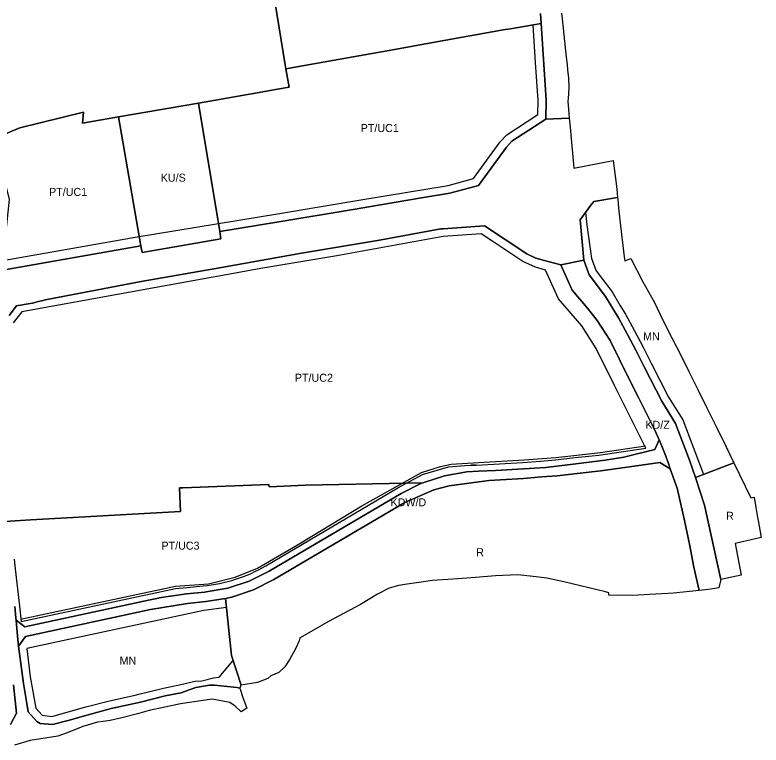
# Model space of a CAD drawing. Extents: x 7436680 to 7439366, y 5548361 to 5550775.
# Drawn here: x 7438434 to 7439366, y 5548558 to 5549471 of the extents above; entities that cross this region are included whole.
import ezdxf

# ---------------------------------------------------------------- set-up
doc = ezdxf.new("R2010")
doc.units = 0
for name, color, linetype in [('linie_rozgraniczajace', 7, 'Continuous'), ('linie_zabudowy_azurowe', 7, 'Continuous'), ('linie_zabudowy_nieprzekraczalne', 7, 'Continuous'), ('oznaczenia_przeznaczen', 7, 'Continuous')]:
    doc.layers.add(name, color=color, linetype=linetype)

msp = doc.modelspace()

# ---------------------------------------------------------------- linework, layer by layer
at = {"layer": 'linie_rozgraniczajace'}
for points in [[(7438758.39, 5549488.21), (7438771.55, 5549408.46), (7438772.42, 5549403.54), (7438772.37, 5549403.53), (7438776.39, 5549380.53), (7438762.06, 5549377.99), (7438736.43, 5549373.59), (7438712.84, 5549369.45), (7438662.92, 5549360.56), (7438563.16, 5549343.44), (7438518.12, 5549335.61), (7438519.44, 5549349.55), (7438440, 5549329.59), (7438398.71, 5549312.9)], [(7439090.49, 5549472.78), (7439091.28, 5549460.46), (7439081.9, 5549458.81), (7439053.2, 5549453.78), (7439046.51, 5549452.59), (7438955.8, 5549436.39), (7438906.16, 5549427.5), (7438856.52, 5549418.6), (7438807.29, 5549409.78), (7438772.42, 5549403.54), (7438771.55, 5549408.46), (7438758.39, 5549488.21)], [(7439116.62, 5549473.09), (7439117.57, 5549466.21), (7439122.55, 5549418.11), (7439123.79, 5549408.88), (7439124.43, 5549401.86), (7439125.43, 5549392.18), (7439125.83, 5549379.29), (7439125.15, 5549366.28), (7439124.52, 5549363.27), (7439125.91, 5549347.92), (7439126.45, 5549341.98), (7439097.19, 5549340.81), (7439097.48, 5549364.34), (7439091.28, 5549460.46), (7439090.49, 5549472.78)], [(7438420.86, 5549152.06), (7438591.21, 5549182.25), (7438592.66, 5549173.93), (7438621.57, 5549178.81), (7438633.67, 5549180.91), (7438691.19, 5549191.04), (7438689.86, 5549200.22), (7438763.32, 5549212.38), (7438853.79, 5549227.43), (7438944.27, 5549242.48), (7438977.15, 5549247.95), (7439012.92, 5549257.77), (7439047.87, 5549305.78), (7439054.9, 5549313.26), (7439097.19, 5549340.81), (7439126.45, 5549341.98), (7439127.48, 5549330.64), (7439129.18, 5549311.96), (7439131.67, 5549284.51), (7439132.15, 5549279.27), (7439181.32, 5549288.86), (7439186.07, 5549253.42), (7439186.93, 5549242.78), (7439157.21, 5549237.85), (7439153.39, 5549233.08), (7439140.09, 5549214.87), (7439144.6, 5549164.19), (7439115.92, 5549158.3), (7439100.32, 5549162.61), (7439084.73, 5549166.92), (7439073.32, 5549172.36), (7439020.58, 5549207.34), (7438968.76, 5549203.62), (7438965.87, 5549203.41), (7438889.32, 5549189.43), (7438887, 5549189.04), (7438791.89, 5549173.1), (7438691.9, 5549155.13), (7438591.6, 5549137.47), (7438475.87, 5549115.65), (7438473.59, 5549115.06), (7438470.21, 5549114.2), (7438468.65, 5549113.81), (7438467.27, 5549113.46), (7438462.9, 5549112.4), (7438457.32, 5549111.09), (7438455.53, 5549110.68), (7438450.12, 5549109.76), (7438445.37, 5549108.86), (7438440.88, 5549107.99), (7438437.8, 5549107.46), (7438435.66, 5549107.09), (7438426.37, 5549095.2)], [(7438426.37, 5549095.2), (7438435.66, 5549107.09), (7438437.8, 5549107.46), (7438440.88, 5549107.99), (7438445.37, 5549108.86), (7438450.12, 5549109.76), (7438455.53, 5549110.68), (7438457.32, 5549111.09), (7438462.9, 5549112.4), (7438467.27, 5549113.46), (7438468.65, 5549113.81), (7438470.21, 5549114.2), (7438473.59, 5549115.06), (7438475.87, 5549115.65), (7438591.6, 5549137.47), (7438691.9, 5549155.13), (7438791.89, 5549173.1), (7438887, 5549189.04), (7438889.32, 5549189.43), (7438965.87, 5549203.41), (7438968.76, 5549203.62), (7439020.58, 5549207.34), (7439073.32, 5549172.36), (7439084.73, 5549166.92), (7439100.32, 5549162.61), (7439115.92, 5549158.3), (7439130.05, 5549126.55), (7439149.34, 5549104.27), (7439161.5, 5549088.8), (7439177.48, 5549063.6), (7439201.05, 5549016.44), (7439213.39, 5548991.75), (7439230.43, 5548957.66), (7439230.68, 5548957.16), (7439230.93, 5548956.66), (7439231.18, 5548956.16), (7439231.42, 5548955.66), (7439231.67, 5548955.16), (7439231.91, 5548954.66), (7439232.16, 5548954.16), (7439232.4, 5548953.66), (7439232.64, 5548953.16), (7439232.89, 5548952.66), (7439233.13, 5548952.16), (7439233.37, 5548951.65), (7439233.61, 5548951.15), (7439233.85, 5548950.65), (7439234.09, 5548950.15), (7439234.32, 5548949.64), (7439234.56, 5548949.14), (7439234.8, 5548948.64), (7439235.03, 5548948.13), (7439235.27, 5548947.63), (7439235.5, 5548947.12), (7439235.73, 5548946.62), (7439235.97, 5548946.11), (7439236.2, 5548945.6), (7439236.43, 5548945.1), (7439236.66, 5548944.59), (7439236.89, 5548944.08), (7439237.12, 5548943.58), (7439237.35, 5548943.07), (7439237.58, 5548942.56), (7439237.8, 5548942.05), (7439238.03, 5548941.54), (7439238.25, 5548941.03), (7439238.48, 5548940.52), (7439238.7, 5548940.01), (7439238.91, 5548939.54), (7439233.43, 5548927.55), (7439194.72, 5548918.03), (7439171.58, 5548914.26), (7439134.72, 5548909.36), (7439097.34, 5548905.11), (7439034.42, 5548901.17), (7439013.09, 5548900.52), (7438998.51, 5548899.54), (7438970.49, 5548894.64), (7438943.44, 5548885.86), (7438943.44, 5548885.86), (7438796.98, 5548882.79), (7438751.28, 5548880.69), (7438750.95, 5548883.88), (7438643.55, 5548879.48), (7438639.45, 5548879.31), (7438640.66, 5548849.84), (7438453.56, 5548839.39), (7438421.02, 5548837.58)], [(7439115.92, 5549158.3), (7439144.6, 5549164.19), (7439151.33, 5549145.97), (7439171.82, 5549119), (7439188.06, 5549091.99), (7439199.19, 5549071.18), (7439209.97, 5549050.74), (7439220.07, 5549030.99), (7439242.02, 5548987.84), (7439259.36, 5548960.09), (7439276.81, 5548914.25), (7439284.15, 5548892.38), (7439295.7, 5548857.98), (7439315.91, 5548764.71), (7439313.53, 5548754.52), (7439300.65, 5548752.42), (7439288.83, 5548751.19), (7439282.04, 5548780.33), (7439276.95, 5548809.24), (7439270.65, 5548838.72), (7439261.28, 5548878.96), (7439252.74, 5548903.34), (7439249.54, 5548912.49), (7439249.51, 5548912.57), (7439249.33, 5548913.09), (7439249.14, 5548913.62), (7439248.96, 5548914.14), (7439248.77, 5548914.67), (7439248.58, 5548915.19), (7439248.39, 5548915.71), (7439248.2, 5548916.24), (7439248.01, 5548916.76), (7439247.82, 5548917.28), (7439247.63, 5548917.81), (7439247.44, 5548918.33), (7439247.25, 5548918.85), (7439247.05, 5548919.37), (7439246.86, 5548919.9), (7439246.66, 5548920.42), (7439246.47, 5548920.94), (7439246.27, 5548921.46), (7439246.08, 5548921.98), (7439245.88, 5548922.5), (7439245.68, 5548923.02), (7439245.48, 5548923.54), (7439245.28, 5548924.06), (7439245.08, 5548924.58), (7439244.88, 5548925.1), (7439244.67, 5548925.62), (7439244.47, 5548926.13), (7439244.27, 5548926.65), (7439244.06, 5548927.17), (7439243.86, 5548927.69), (7439243.65, 5548928.2), (7439243.44, 5548928.72), (7439243.24, 5548929.24), (7439243.22, 5548929.28), (7439243.03, 5548929.75), (7439242.82, 5548930.27), (7439242.61, 5548930.79), (7439242.4, 5548931.3), (7439242.19, 5548931.82), (7439241.97, 5548932.33), (7439241.76, 5548932.85), (7439241.55, 5548933.36), (7439241.33, 5548933.87), (7439241.12, 5548934.39), (7439240.9, 5548934.9), (7439240.68, 5548935.41), (7439240.47, 5548935.93), (7439240.25, 5548936.44), (7439240.03, 5548936.95), (7439239.81, 5548937.46), (7439239.59, 5548937.97), (7439239.37, 5548938.48), (7439239.15, 5548938.99), (7439238.93, 5548939.5), (7439238.91, 5548939.54), (7439238.7, 5548940.01), (7439238.48, 5548940.52), (7439238.25, 5548941.03), (7439238.03, 5548941.54), (7439237.8, 5548942.05), (7439237.58, 5548942.56), (7439237.35, 5548943.07), (7439237.12, 5548943.58), (7439236.89, 5548944.08), (7439236.66, 5548944.59), (7439236.43, 5548945.1), (7439236.2, 5548945.6), (7439235.97, 5548946.11), (7439235.73, 5548946.62), (7439235.5, 5548947.12), (7439235.27, 5548947.63), (7439235.03, 5548948.13), (7439234.8, 5548948.64), (7439234.56, 5548949.14), (7439234.32, 5548949.64), (7439234.09, 5548950.15), (7439233.85, 5548950.65)], [(7439233.85, 5548950.65), (7439233.61, 5548951.15), (7439233.37, 5548951.65), (7439233.13, 5548952.16), (7439232.89, 5548952.66), (7439232.64, 5548953.16), (7439232.4, 5548953.66), (7439232.16, 5548954.16), (7439231.91, 5548954.66), (7439231.67, 5548955.16), (7439231.42, 5548955.66), (7439231.18, 5548956.16), (7439230.93, 5548956.66), (7439230.68, 5548957.16), (7439230.43, 5548957.66), (7439213.39, 5548991.75), (7439201.05, 5549016.44), (7439177.48, 5549063.6), (7439161.5, 5549088.8), (7439149.34, 5549104.27), (7439130.05, 5549126.55), (7439115.92, 5549158.3)], [(7438435.1, 5548713.87), (7438446.18, 5548705.73), (7438600.78, 5548738.94), (7438612.95, 5548741.55), (7438613.84, 5548741.74), (7438648.31, 5548746.98), (7438670.99, 5548749.12), (7438672.55, 5548749.27), (7438699.97, 5548754.08), (7438726.42, 5548762.77), (7438751.35, 5548775.16), (7438916.46, 5548872.54), (7438941.91, 5548885.23), (7438943.44, 5548885.86), (7438943.44, 5548885.86), (7438970.49, 5548894.64), (7438998.51, 5548899.54), (7439013.09, 5548900.52), (7439034.42, 5548901.17), (7439097.34, 5548905.11), (7439134.72, 5548909.36), (7439171.58, 5548914.26), (7439194.72, 5548918.03), (7439233.43, 5548927.55), (7439238.91, 5548939.54), (7439238.93, 5548939.5), (7439239.15, 5548938.99), (7439239.37, 5548938.48), (7439239.59, 5548937.97), (7439239.81, 5548937.46), (7439240.03, 5548936.95), (7439240.25, 5548936.44), (7439240.47, 5548935.93), (7439240.68, 5548935.41), (7439240.9, 5548934.9), (7439241.12, 5548934.39), (7439241.33, 5548933.87), (7439241.55, 5548933.36), (7439241.76, 5548932.85), (7439241.97, 5548932.33), (7439242.19, 5548931.82), (7439242.4, 5548931.3), (7439242.61, 5548930.79), (7439242.82, 5548930.27), (7439243.03, 5548929.75), (7439243.22, 5548929.28), (7439243.24, 5548929.24), (7439243.44, 5548928.72), (7439243.65, 5548928.2), (7439243.86, 5548927.69), (7439244.06, 5548927.17), (7439244.27, 5548926.65), (7439244.47, 5548926.13), (7439244.67, 5548925.62), (7439244.88, 5548925.1), (7439245.08, 5548924.58), (7439245.28, 5548924.06), (7439245.48, 5548923.54), (7439245.68, 5548923.02), (7439245.88, 5548922.5), (7439246.08, 5548921.98), (7439246.27, 5548921.46), (7439246.47, 5548920.94), (7439246.66, 5548920.42), (7439246.86, 5548919.9), (7439247.05, 5548919.37), (7439247.25, 5548918.85), (7439247.44, 5548918.33), (7439247.63, 5548917.81), (7439247.82, 5548917.28), (7439248.01, 5548916.76), (7439248.2, 5548916.24), (7439248.39, 5548915.71), (7439248.58, 5548915.19), (7439248.77, 5548914.67), (7439248.96, 5548914.14), (7439249.14, 5548913.62), (7439249.33, 5548913.09), (7439249.51, 5548912.57), (7439249.54, 5548912.49), (7439252.74, 5548903.34), (7439239.87, 5548911.25), (7439204.53, 5548906.22), (7439165.82, 5548900.71), (7439136.24, 5548897.46), (7439111.35, 5548894.63), (7439092.11, 5548893.11), (7439069.28, 5548891.38), (7439040.43, 5548889.67), (7439026, 5548888.82), (7438976.32, 5548882.2), (7438957.23, 5548876.92), (7438921.01, 5548861.29), (7438757.44, 5548764.82), (7438731.78, 5548752.01), (7438704.58, 5548742.88), (7438696.68, 5548740.99), (7438672.11, 5548737.17), (7438649.44, 5548735.04), (7438603.3, 5548727.2)], [(7438421.02, 5548837.58), (7438453.56, 5548839.39), (7438640.66, 5548849.84), (7438639.45, 5548879.31), (7438643.55, 5548879.48), (7438750.95, 5548883.88), (7438751.28, 5548880.69), (7438796.98, 5548882.79), (7438943.44, 5548885.86), (7438941.91, 5548885.23), (7438916.46, 5548872.54), (7438751.35, 5548775.16), (7438726.42, 5548762.77), (7438699.97, 5548754.08), (7438672.55, 5548749.27), (7438670.99, 5548749.12), (7438648.31, 5548746.98), (7438613.84, 5548741.74), (7438612.95, 5548741.55), (7438600.78, 5548738.94), (7438446.18, 5548705.73), (7438435.1, 5548713.87), (7438434.81, 5548717.07), (7438433.39, 5548730.97)], [(7438433.39, 5548730.97), (7438434.81, 5548717.07), (7438435.1, 5548713.87), (7438436.06, 5548703.54), (7438437.77, 5548685.03), (7438438.22, 5548681.56), (7438441.03, 5548659.83), (7438444.29, 5548634.64), (7438448.2, 5548612.09), (7438450.44, 5548599.21), (7438461.11, 5548587.44), (7438465.04, 5548584.65), (7438480.77, 5548583.51), (7438500.33, 5548588.52), (7438525.08, 5548595.78), (7438554.1, 5548603.3), (7438590.82, 5548611.6), (7438621.52, 5548619.15), (7438641.45, 5548623.01), (7438651.33, 5548626.69), (7438659.59, 5548629.77), (7438676.76, 5548632.77), (7438682.99, 5548632.7), (7438711.63, 5548629.86), (7438714.86, 5548629.11), (7438718.45, 5548617.07), (7438723.55, 5548603.76), (7438716.27, 5548599.14), (7438708.75, 5548606.54), (7438702.33, 5548611.19), (7438680.2, 5548615.06), (7438640.5, 5548609.34), (7438601.58, 5548600.8), (7438586.78, 5548596.71), (7438567.41, 5548592.02), (7438552.57, 5548588.43), (7438544.1, 5548587.35), (7438536.7, 5548586.4), (7438518.41, 5548581.02), (7438498.83, 5548573.22), (7438487.44, 5548568.94), (7438452.9, 5548563.64), (7438433.18, 5548557.74)], [(7438603.3, 5548727.2), (7438446.71, 5548693.58), (7438438.22, 5548681.56), (7438437.77, 5548685.03), (7438436.06, 5548703.54), (7438435.1, 5548713.87)], [(7438431.81, 5548633.26), (7438435.76, 5548597.64), (7438427.97, 5548583.58)], [(7438427.97, 5548583.58), (7438435.76, 5548597.64), (7438431.81, 5548633.26)]]:
    msp.add_lwpolyline(points, dxfattribs=at)
for points in [[(7438662.92, 5549360.56), (7438712.84, 5549369.45), (7438736.43, 5549373.59), (7438762.06, 5549377.99), (7438776.39, 5549380.53), (7438772.37, 5549403.53), (7438772.42, 5549403.54), (7438807.29, 5549409.78), (7438856.52, 5549418.6), (7438906.16, 5549427.5), (7438955.8, 5549436.39), (7439046.51, 5549452.59), (7439053.2, 5549453.78), (7439081.9, 5549458.81), (7439091.28, 5549460.46), (7439097.48, 5549364.34), (7439097.19, 5549340.81), (7439054.9, 5549313.26), (7439047.87, 5549305.78), (7439012.92, 5549257.77), (7438977.15, 5549247.95), (7438944.27, 5549242.48), (7438853.79, 5549227.43), (7438763.32, 5549212.38), (7438689.86, 5549200.22)], [(7438563.16, 5549343.44), (7438662.92, 5549360.56), (7438689.86, 5549200.22), (7438691.19, 5549191.04), (7438633.67, 5549180.91), (7438621.57, 5549178.81), (7438592.66, 5549173.93), (7438591.21, 5549182.25)], [(7438398.71, 5549312.9), (7438440, 5549329.59), (7438519.44, 5549349.55), (7438518.12, 5549335.61), (7438563.16, 5549343.44), (7438591.21, 5549182.25), (7438420.86, 5549152.06), (7438407.75, 5549164.35), (7438416.17, 5549239.74)], [(7439140.09, 5549214.87), (7439153.39, 5549233.08), (7439157.21, 5549237.85), (7439186.93, 5549242.78), (7439187.1, 5549240.61), (7439187.97, 5549229.87), (7439190.64, 5549207.03), (7439195.28, 5549168.51), (7439195.88, 5549163.55), (7439203.27, 5549166.47), (7439218.11, 5549138.16), (7439233.09, 5549111.29), (7439243.37, 5549089.04), (7439254.76, 5549067.2), (7439265.82, 5549045.42), (7439276.53, 5549024.37), (7439287.35, 5549002.4), (7439298.62, 5548979.53), (7439311.32, 5548953.53), (7439322.08, 5548931.51), (7439332.24, 5548910.72), (7439284.15, 5548892.38), (7439276.81, 5548914.25), (7439259.36, 5548960.09), (7439242.02, 5548987.84), (7439220.07, 5549030.99), (7439209.97, 5549050.74), (7439199.19, 5549071.18), (7439188.06, 5549091.99), (7439171.82, 5549119), (7439151.33, 5549145.97), (7439144.6, 5549164.19)], [(7438696.68, 5548740.99), (7438704.58, 5548742.88), (7438731.78, 5548752.01), (7438757.44, 5548764.82), (7438921.01, 5548861.29), (7438957.23, 5548876.92), (7438976.32, 5548882.2), (7439026, 5548888.82), (7439040.43, 5548889.67), (7439069.28, 5548891.38), (7439092.11, 5548893.11), (7439111.35, 5548894.63), (7439136.24, 5548897.46), (7439165.82, 5548900.71), (7439204.53, 5548906.22), (7439239.87, 5548911.25), (7439252.74, 5548903.34), (7439261.28, 5548878.96), (7439270.65, 5548838.72), (7439276.95, 5548809.24), (7439282.04, 5548780.33), (7439288.83, 5548751.19), (7439256.72, 5548747.83), (7439242.14, 5548746.89), (7439205.26, 5548744.9), (7439176.11, 5548745.37), (7439176.05, 5548748.16), (7439171.79, 5548749.47), (7439119.8, 5548761.94), (7439098.33, 5548766.53), (7439085.1, 5548768.07), (7439062.37, 5548770.62), (7439034.22, 5548769.43), (7439009.21, 5548767.44), (7438987.32, 5548765.69), (7438961.84, 5548764.07), (7438955.69, 5548763.7), (7438938.33, 5548761.21), (7438920.99, 5548758.59), (7438916.09, 5548757.73), (7438912.88, 5548757.2), (7438901.46, 5548754), (7438886.67, 5548746.48), (7438865.39, 5548733.47), (7438825.43, 5548712.31), (7438790.14, 5548691.89), (7438789.83, 5548691.71), (7438788.99, 5548688.08), (7438784.47, 5548677.97), (7438777.38, 5548665.06), (7438771.21, 5548655.6), (7438763.58, 5548648.6), (7438753.59, 5548644.27), (7438749.64, 5548641.02), (7438736.9, 5548636.23), (7438716.48, 5548632.68), (7438704.2, 5548669.75)], [(7439284.15, 5548892.38), (7439332.24, 5548910.72), (7439353.56, 5548867.06), (7439357.49, 5548867.92), (7439359.65, 5548855.11), (7439361.79, 5548842.41), (7439362.44, 5548838.62), (7439366.25, 5548817.4), (7439359.18, 5548815.81), (7439333.69, 5548809.85), (7439341.54, 5548770.47), (7439315.98, 5548765), (7439315.91, 5548764.71), (7439295.7, 5548857.98)], [(7438438.22, 5548681.56), (7438446.71, 5548693.58), (7438603.3, 5548727.2), (7438649.44, 5548735.04), (7438672.11, 5548737.17), (7438696.68, 5548740.99), (7438704.2, 5548669.75), (7438716.48, 5548632.68), (7438716.19, 5548632.63), (7438714.86, 5548629.11), (7438711.63, 5548629.86), (7438682.99, 5548632.7), (7438676.76, 5548632.77), (7438659.59, 5548629.77), (7438651.33, 5548626.69), (7438641.45, 5548623.01), (7438621.52, 5548619.15), (7438590.82, 5548611.6), (7438554.1, 5548603.3), (7438525.08, 5548595.78), (7438500.33, 5548588.52), (7438480.77, 5548583.51), (7438465.04, 5548584.65), (7438461.11, 5548587.44), (7438450.44, 5548599.21), (7438448.2, 5548612.09), (7438444.29, 5548634.64), (7438441.03, 5548659.83)]]:
    msp.add_lwpolyline(points, close=True, dxfattribs=at)
at = {"layer": 'linie_zabudowy_azurowe'}
for points in [[(7438790.85, 5548810.89), (7438867.15, 5548856.82), (7438941.77, 5548898.85), (7438965.49, 5548906.06), (7438978.83, 5548909.03), (7439013.05, 5548911.01), (7439070.34, 5548914.42), (7439109.78, 5548917.52), (7439165.63, 5548923.72), (7439221.86, 5548932.01)], [(7438441.31, 5548712.36), (7438634.39, 5548753.74)]]:
    msp.add_lwpolyline(points, dxfattribs=at)
at = {"layer": 'linie_zabudowy_nieprzekraczalne'}
for points in [[(7438408.09, 5549316.69), (7438416.26, 5549282.45), (7438426.4, 5549239.95), (7438418.62, 5549165.26), (7438418.46, 5549163.74), (7438586.64, 5549193.27), (7438761.68, 5549222.25), (7438868.34, 5549239.99), (7438975, 5549257.73), (7439006.9, 5549266.48), (7439040.16, 5549312.18), (7439048.44, 5549320.99), (7439087.26, 5549346.27), (7439087.48, 5549364.08), (7439084.43, 5549411.4), (7439081.38, 5549458.72)], [(7439146.62, 5549223.81), (7439148.64, 5549208.39), (7439154.44, 5549166.41), (7439160.19, 5549150.84), (7439175.85, 5549130.21), (7439180.11, 5549124.61), (7439189.77, 5549107.96), (7439196.76, 5549096.93), (7439208.02, 5549075.87), (7439218.84, 5549055.35), (7439228.98, 5549035.53), (7439250.73, 5548992.77), (7439268.35, 5548964.56), (7439293.96, 5548897.3)], [(7438969.09, 5549193.68), (7438835.85, 5549169.62)], [(7439016.44, 5549197.08), (7438969.09, 5549193.68)], [(7439030.87, 5549187.54), (7439016.44, 5549197.08)], [(7439030.87, 5549187.54), (7439016.44, 5549197.08)], [(7439068.56, 5549162.62), (7439030.87, 5549187.54)], [(7438835.85, 5549169.62), (7438743.61, 5549154.27)], [(7439084.41, 5549155.65), (7439068.56, 5549162.62)], [(7439096.86, 5549151.66), (7439084.41, 5549155.65)], [(7438743.61, 5549154.27), (7438442.26, 5549099.57)], [(7439112.99, 5549115.71), (7439096.86, 5549151.66)], [(7439142.05, 5549082.13), (7439112.99, 5549115.71)], [(7438442.26, 5549099.57), (7438431.39, 5549085.71)], [(7439160.05, 5549053.75), (7439142.05, 5549082.13)], [(7439183.16, 5549007.5), (7439160.05, 5549053.75)], [(7439222.42, 5548928.96), (7439183.16, 5549007.5)], [(7439163.32, 5548920.55), (7439222.42, 5548928.96)], [(7439067.93, 5548911.33), (7439090.57, 5548913.05)], [(7439090.57, 5548913.05), (7439109.43, 5548914.54)], [(7439109.43, 5548914.54), (7439134.02, 5548917.33)], [(7439134.02, 5548917.33), (7439163.32, 5548920.55)], [(7438943.24, 5548896.03), (7438975.54, 5548905.62)], [(7438975.54, 5548905.62), (7438995.91, 5548907.33)], [(7438995.91, 5548907.33), (7439009.83, 5548907.92)], [(7439003.57, 5548907.7), (7439010.64, 5548907.94)], [(7439009.83, 5548907.92), (7439003.57, 5548907.7)], [(7439010.64, 5548907.94), (7439067.93, 5548911.33)], [(7438912.4, 5548879.43), (7438943.24, 5548896.03)], [(7438747.28, 5548782.05), (7438912.4, 5548879.43)], [(7438440.85, 5548715.04), (7438634.22, 5548756.63), (7438675.65, 5548759.27), (7438708.89, 5548767.72), (7438736.94, 5548779.23), (7438794.59, 5548812.71)], [(7438432.65, 5548790.37), (7438434.18, 5548778.15)], [(7438434.18, 5548778.15), (7438439.36, 5548731.61)], [(7438634.39, 5548753.74), (7438648.5, 5548754.69)], [(7438648.5, 5548754.69), (7438668.95, 5548756.96)], [(7438439.36, 5548731.61), (7438441.31, 5548712.36)], [(7438698.13, 5548729.72), (7438669.85, 5548726.16), (7438448.62, 5548678.64)], [(7438448.62, 5548678.64), (7438452.94, 5548643.27)], [(7438682, 5548641.97), (7438688.92, 5548642.52), (7438702.33, 5548658.51), (7438706.06, 5548663.2)], [(7438452.94, 5548643.27), (7438459.79, 5548603.78)], [(7438619.37, 5548628.92), (7438641.11, 5548633.56)], [(7438641.11, 5548633.56), (7438659.14, 5548637.5)], [(7438659.14, 5548637.5), (7438667.38, 5548638.18)], [(7438667.38, 5548638.18), (7438682, 5548641.97)], [(7438588.43, 5548621.32), (7438619.37, 5548628.92)], [(7438551.75, 5548613.02), (7438583.93, 5548620.3)], [(7438583.93, 5548620.3), (7438588.43, 5548621.32)], [(7438479.86, 5548593.6), (7438522.42, 5548605.42)], [(7438522.42, 5548605.42), (7438551.75, 5548613.02)], [(7438459.79, 5548603.78), (7438467.79, 5548594.96)], [(7438467.79, 5548594.96), (7438479.86, 5548593.6)]]:
    msp.add_lwpolyline(points, dxfattribs=at)
msp.add_arc((7438652.8, 5548942.21), 185.95, 274.98378, 300.53794, dxfattribs=at)

# ---------------------------------------------------------------- texts
at = {"layer": 'oznaczenia_przeznaczen'}
for s, p in [('PT/UC1', (7438865.87, 5549324.54)), ('KU/S', (7438615.98, 5549262.41)), ('PT/UC1', (7438476.36, 5549244.67)), ('MN', (7439218.77, 5549064.2)), ('PT/UC2', (7438783.58, 5549012.2)), ('KD/Z', (7439221.68, 5548953.36)), ('KDW/D', (7438903.14, 5548856.37)), ('R', (7439322.45, 5548839.53)), ('PT/UC3', (7438616.82, 5548802.2)), ('R', (7439010.28, 5548793.96)), ('MN', (7438564.53, 5548658.45))]:
    msp.add_text(s, height=10, dxfattribs=at).set_placement(p)

doc.saveas('drawing.dxf')
